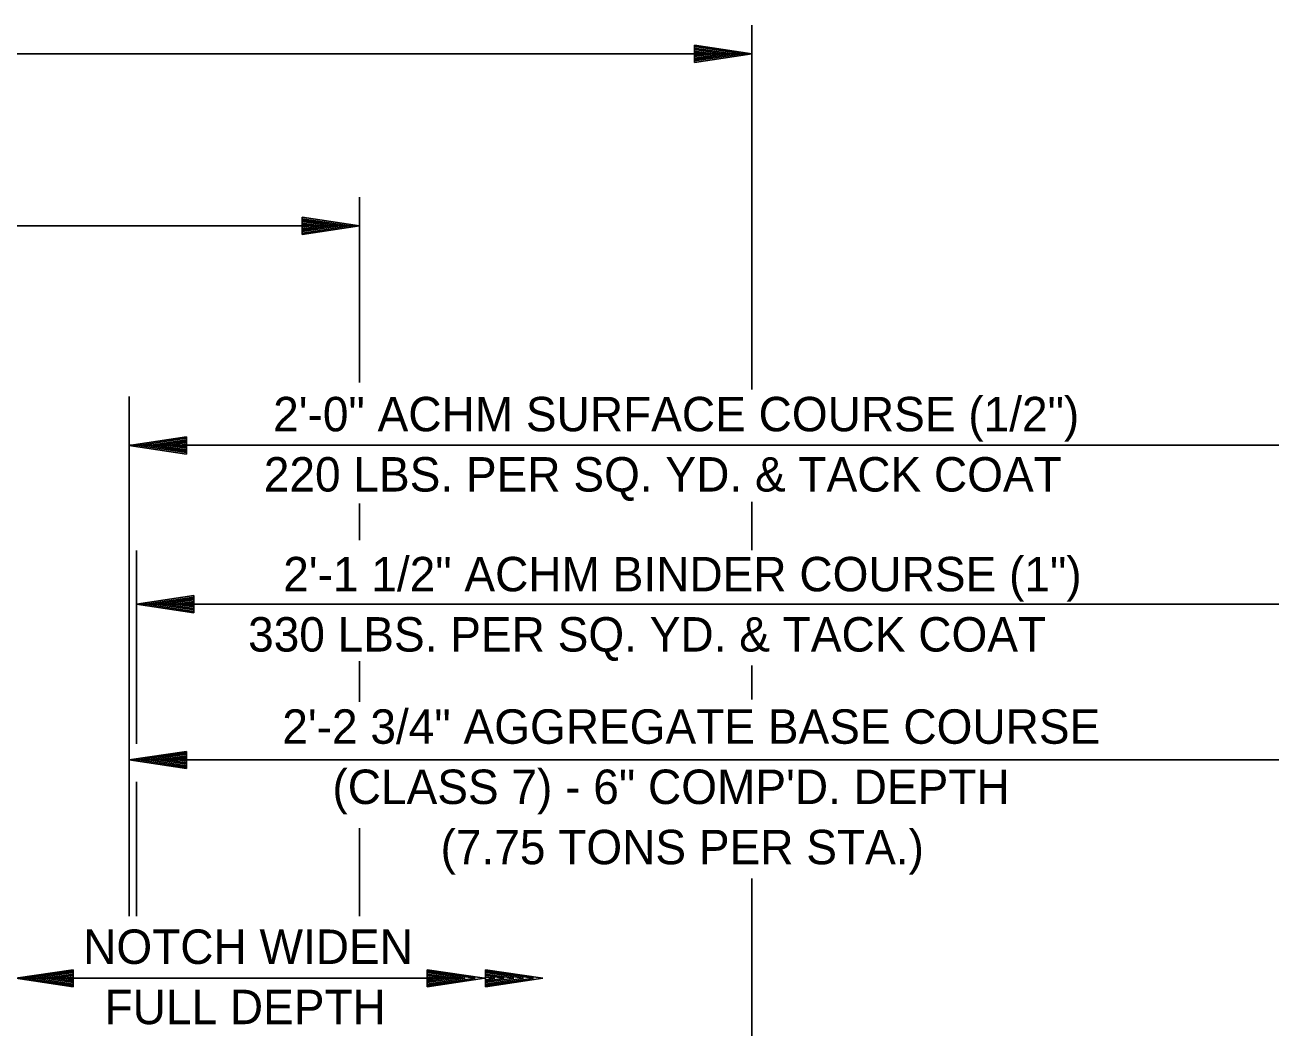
# Model space of a CAD drawing. Extents: x -900 to 15312, y 1857 to 2945.
# Drawn here: x 2232.9 to 2451.5, y 2258.2 to 2432.9 of the extents above; entities that cross this region are included whole.
import ezdxf

# ---------------------------------------------------------------- set-up
doc = ezdxf.new("R2010")
doc.units = 0
doc.layers.add('R_Annotation', color=7, linetype='Continuous')
doc.layers.add('R_Dimension', color=7, linetype='Continuous')

msp = doc.modelspace()

# ---------------------------------------------------------------- linework, layer by layer
at = {"layer": 'R_Dimension'}
for p, q in [((2359.6, 2369.42), (2359.6, 2432.95)), ((2349.6, 2429.45), (2359.6, 2427.95)), ((2349.6, 2429.45), (2349.6, 2426.45)), ((2349.6, 2429.2), (2357.93, 2427.95)), ((2349.6, 2428.94), (2356.21, 2427.95)), ((2349.6, 2428.69), (2354.55, 2427.95)), ((1922.75, 2427.95), (2359.6, 2427.95)), ((2349.6, 2428.43), (2352.85, 2427.95)), ((2349.6, 2428.18), (2351.18, 2427.95)), ((2349.6, 2426.45), (2359.6, 2427.95)), ((2349.6, 2427.46), (2352.85, 2427.95)), ((2349.6, 2426.95), (2356.21, 2427.95)), ((2349.6, 2426.7), (2357.93, 2427.95)), ((2349.6, 2427.2), (2354.55, 2427.95)), ((2349.6, 2427.71), (2351.18, 2427.95)), ((2291.18, 2370.65), (2291.18, 2402.95)), ((2291.18, 2397.95), (1991.17, 2397.95)), ((2281.18, 2399.45), (2291.18, 2397.95)), ((2281.18, 2396.45), (2281.18, 2399.45)), ((2281.18, 2399.2), (2289.51, 2397.95)), ((2281.18, 2398.94), (2287.79, 2397.95)), ((2281.18, 2398.69), (2286.12, 2397.95)), ((2281.18, 2398.44), (2284.43, 2397.95)), ((2281.18, 2398.18), (2282.76, 2397.95)), ((2281.18, 2396.45), (2291.18, 2397.95)), ((2281.18, 2397.46), (2284.43, 2397.95)), ((2281.18, 2396.95), (2287.79, 2397.95)), ((2281.18, 2396.7), (2289.51, 2397.95)), ((2281.18, 2397.2), (2286.12, 2397.95)), ((2281.18, 2397.71), (2282.76, 2397.95)), ((2251.04, 2277.62), (2251.04, 2368.23)), ((2261.04, 2361.19), (2251.04, 2359.69)), ((2261.04, 2360.94), (2252.71, 2359.69)), ((2261.04, 2358.19), (2261.04, 2361.19)), ((2251.04, 2359.76), (2451.46, 2359.76)), ((2261.04, 2358.19), (2251.04, 2359.69)), ((2261.04, 2358.44), (2252.71, 2359.69)), ((2261.04, 2360.68), (2254.43, 2359.69)), ((2261.04, 2358.69), (2254.43, 2359.69)), ((2261.04, 2360.43), (2256.1, 2359.69)), ((2261.04, 2358.94), (2256.1, 2359.69)), ((2261.04, 2360.18), (2257.79, 2359.69)), ((2261.04, 2359.2), (2257.79, 2359.69)), ((2261.04, 2359.92), (2259.46, 2359.69)), ((2261.04, 2359.45), (2259.46, 2359.69)), ((2359.6, 2341.41), (2359.6, 2349.85)), ((2291.18, 2343.19), (2291.18, 2349.56)), ((2252.31, 2307.68), (2252.31, 2341.39)), ((2262.31, 2333.52), (2252.31, 2332.02)), ((2262.31, 2333.27), (2253.98, 2332.02)), ((2262.31, 2333.02), (2255.7, 2332.02)), ((2262.31, 2332.77), (2257.36, 2332.02)), ((2262.31, 2332.51), (2259.06, 2332.02)), ((2262.31, 2330.52), (2262.31, 2333.52)), ((2262.31, 2330.52), (2252.31, 2332.02)), ((2252.31, 2332.02), (2451.46, 2332.02)), ((2262.31, 2330.77), (2253.98, 2332.02)), ((2262.31, 2331.03), (2255.7, 2332.02)), ((2262.31, 2331.28), (2257.36, 2332.02)), ((2262.31, 2331.54), (2259.06, 2332.02)), ((2262.31, 2332.26), (2260.73, 2332.02)), ((2262.31, 2331.79), (2260.73, 2332.02)), ((2291.18, 2314.99), (2291.18, 2322.11)), ((2359.6, 2315.41), (2359.6, 2321.31)), ((2261.04, 2306.37), (2251.04, 2304.87)), ((2261.04, 2306.12), (2252.71, 2304.87)), ((2261.04, 2303.37), (2261.04, 2306.37)), ((2261.04, 2303.37), (2251.04, 2304.87)), ((2251.04, 2304.87), (2451.46, 2304.87)), ((2261.04, 2303.62), (2252.71, 2304.87)), ((2261.04, 2305.86), (2254.43, 2304.87)), ((2261.04, 2303.87), (2254.43, 2304.87)), ((2261.04, 2305.61), (2256.1, 2304.87)), ((2261.04, 2304.12), (2256.1, 2304.87)), ((2261.04, 2305.36), (2257.79, 2304.87)), ((2261.04, 2304.38), (2257.79, 2304.87)), ((2261.04, 2305.1), (2259.46, 2304.87)), ((2261.04, 2304.63), (2259.46, 2304.87)), ((2252.31, 2277.63), (2252.31, 2301.05)), ((2291.18, 2277.63), (2291.18, 2292.98)), ((2359.6, 2213.92), (2359.6, 2284.18)), ((1868.55, 2266.81), (2309.56, 2266.81)), ((2241.25, 2268.31), (2231.25, 2266.81)), ((2241.25, 2265.31), (2231.25, 2266.81)), ((2241.25, 2268.06), (2232.92, 2266.81)), ((2241.25, 2265.56), (2232.92, 2266.81)), ((2241.25, 2267.8), (2234.64, 2266.81)), ((2241.25, 2265.81), (2234.64, 2266.81)), ((2241.25, 2267.55), (2236.3, 2266.81)), ((2241.25, 2266.06), (2236.3, 2266.81)), ((2241.25, 2267.3), (2238, 2266.81)), ((2241.25, 2266.32), (2238, 2266.81)), ((2241.25, 2267.04), (2239.67, 2266.81)), ((2241.25, 2266.57), (2239.67, 2266.81)), ((2241.25, 2265.31), (2241.25, 2268.31)), ((2303, 2268.31), (2313, 2266.81)), ((2303, 2265.31), (2303, 2268.31)), ((2303, 2268.06), (2311.33, 2266.81)), ((2303, 2267.8), (2309.61, 2266.81)), ((2303, 2267.55), (2307.95, 2266.81)), ((2303, 2267.3), (2306.25, 2266.81)), ((2303, 2267.04), (2304.58, 2266.81)), ((2303, 2265.31), (2313, 2266.81)), ((2303, 2266.32), (2306.25, 2266.81)), ((2303, 2265.81), (2309.61, 2266.81)), ((2303, 2265.56), (2311.33, 2266.81)), ((2303, 2266.06), (2307.95, 2266.81)), ((2303, 2266.57), (2304.58, 2266.81)), ((2313.17, 2268.31), (2323.17, 2266.81)), ((2313.17, 2265.31), (2313.17, 2268.31)), ((2313.17, 2268.06), (2321.5, 2266.81)), ((2313.17, 2267.8), (2319.78, 2266.81)), ((2313.17, 2267.55), (2318.11, 2266.81)), ((2313.17, 2267.3), (2316.42, 2266.81)), ((2313.17, 2267.04), (2314.75, 2266.81)), ((2313.17, 2265.31), (2323.17, 2266.81)), ((2313.17, 2266.32), (2316.42, 2266.81)), ((2313.17, 2265.81), (2319.78, 2266.81)), ((2313.17, 2265.56), (2321.5, 2266.81)), ((2313.17, 2266.06), (2318.11, 2266.81)), ((2313.17, 2266.57), (2314.75, 2266.81))]:
    msp.add_line(p, q, dxfattribs=at)

# ---------------------------------------------------------------- texts
at = {"layer": 'R_Annotation'}
for s, p in [('2\'-0" ACHM SURFACE COURSE (1/2")', (2276.13, 2362.15)), ('220 LBS. PER SQ. YD. & TACK COAT', (2274.5, 2351.65)), ('2\'-1 1/2" ACHM BINDER COURSE (1")', (2277.88, 2334.26)), ('330 LBS. PER SQ. YD. & TACK COAT', (2271.76, 2323.76)), ('2\'-2 3/4" AGGREGATE BASE COURSE', (2277.72, 2307.69)), ('(CLASS 7) - 6" COMP\'D. DEPTH', (2286.46, 2297.19)), ('(7.75 TONS PER STA.)', (2305.31, 2286.69)), ('NOTCH WIDEN ', (2243, 2269.32)), ('FULL DEPTH', (2246.73, 2258.82))]:
    msp.add_text(s, height=6, dxfattribs=at).set_placement(p)

doc.saveas('drawing.dxf')
